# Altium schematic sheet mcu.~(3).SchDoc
size A3
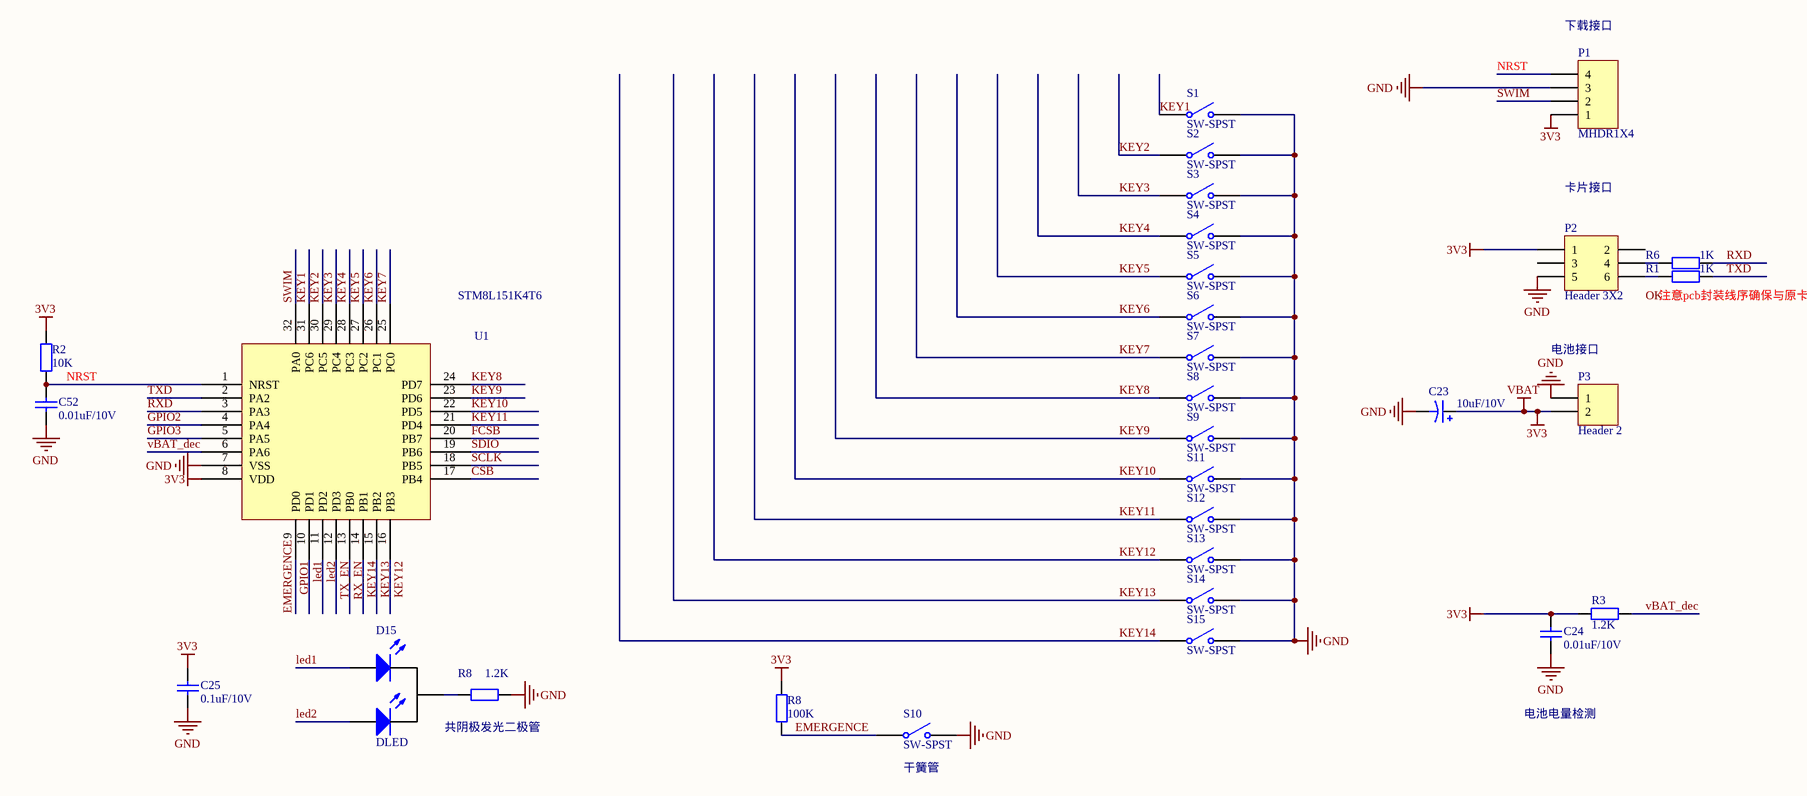
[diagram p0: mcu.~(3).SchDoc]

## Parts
(Parts that share a designator on the sheet are numbered #1, #2 ... from top to bottom, then left to right.)
C23  10uF/10V
C24  0.01uF/10V  [0603C]
C25  0.1uF/10V  [0603C]
C52  0.01uF/10V  [0603C]
D15  DLED
P1  MHDR1X4  [SIP4]
P2  Header 3X2
P3  Header 2
R1  1K  [0603R]
R2  10K  [0603R]
R3  1.2K  [0603R]
R6  1K  [0603R]
R8#1  100K  [0603R]
R8#2  1.2K  [0603R]
S1  SW-SPST
S2  SW-SPST
S3  SW-SPST
S4  SW-SPST
S5  SW-SPST
S6  SW-SPST
S7  SW-SPST
S8  SW-SPST
S9  SW-SPST
S10  SW-SPST
S11  SW-SPST
S12  SW-SPST
S13  SW-SPST
S14  SW-SPST
S15  SW-SPST
U1  STM8L151K4T6  [QFP80P900X900X245-32N]

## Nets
3V3: C23.1 C24.1 C25.1 P1.1 P2.1 P3.2 R2.2 R3.2 R8#1.1 U1.8(VDD)  [also labelled VBAT]
GND: C23.2 C24.2 C25.2 C52.2 P1.3 P2.5 P3.1 R8#2.1 S1.2(NO) S2.2(NO) S3.2(NO) S4.2(NO) S5.2(NO) S6.2(NO) S7.2(NO) S8.2(NO) S9.2(NO) S10.2(NO) S11.2(NO) S12.2(NO) S13.2(NO) S14.2(NO) S15.2(NO) U1.7(VSS)
CSB: U1.17(PB4)
EMERGENCE: R8#1.2 S10.1(COMMON) U1.9(PD0)  [also labelled GPIO1]
FCSB: U1.20(PB7)
GPIO2: U1.4(PA4)
GPIO3: U1.5(PA5)
KEY1: S1.1(COMMON) U1.31(PC6)
KEY2: S2.1(COMMON) U1.30(PC5)
KEY3: S3.1(COMMON) U1.29(PC4)
KEY4: S4.1(COMMON) U1.28(PC3)
KEY5: S5.1(COMMON) U1.27(PC2)
KEY6: S6.1(COMMON) U1.26(PC1)
KEY7: S7.1(COMMON) U1.25(PC0)
KEY8: S8.1(COMMON) U1.24(PD7)
KEY9: S9.1(COMMON) U1.23(PD6)
KEY10: S11.1(COMMON) U1.22(PD5)
KEY11: S12.1(COMMON) U1.21(PD4)
KEY12: S13.1(COMMON) U1.16(PB3)
KEY13: S14.1(COMMON) U1.15(PB2)
KEY14: S15.1(COMMON) U1.14(PB1)
led1: D15.1(A) U1.10(PD1)
led2: D15.3(A) U1.11(PD2)
NRST: C52.1 P1.4 R2.1 U1.1(NRST)
RX_EN: U1.13(PB0)
RXD: R6.1 U1.3(PA3)
SCLK: U1.18(PB5)
SDIO: U1.19(PB6)
SWIM: P1.2 U1.32(PA0)
TX_EN: U1.12(PD3)
TXD: R1.1 U1.2(PA2)
vBAT_dec: R3.1 U1.6(PA6)
NetD15_2: D15.2(K) R8#2.2
NetP2_4: P2.4 R6.2
NetP2_6: P2.6 R1.2

Not connected (* = marked no-connect by the designer): P2 2 3

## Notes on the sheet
- (near P1) 下载接口
- 卡片接口
- (near R1) 注意pcb封装线序确保与原卡片接口一致
- (near P3) 电池接口
- 共阴极发光二极管
- 电池电量检测
- (near S10) 干簧管
- Labels drawn without touching a wire or pin: OK

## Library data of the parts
C23 = Cap Pol1: Polarized Capacitor (Radial); Value: 100pF
C24 C25 C52 = Cap: Capacitor; Value: 106
P1 = MHDR1X4: Header, 4-Pin
P2 = Header 3X2: Header, 3-Pin, Dual row
P3 = Header 2: Header, 2-Pin
R1-R3 R6 R8#1 R8#2 = Res2: Resistor; Value: 10K/5%/1/8W
S1-S15 = SW-SPST: Single-Pole, Single-Throw Switch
